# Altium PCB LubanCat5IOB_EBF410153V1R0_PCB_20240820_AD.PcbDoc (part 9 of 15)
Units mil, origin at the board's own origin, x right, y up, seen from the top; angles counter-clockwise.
Board outline 6811.02 x 4055.12 mil, 6 copper layers (TOP, GND02, ART03, ART04, PWR05, BOTTOM), stack 59.279 mil thick; 981 components, 783 nets, 3627 pads, 2669 vias.
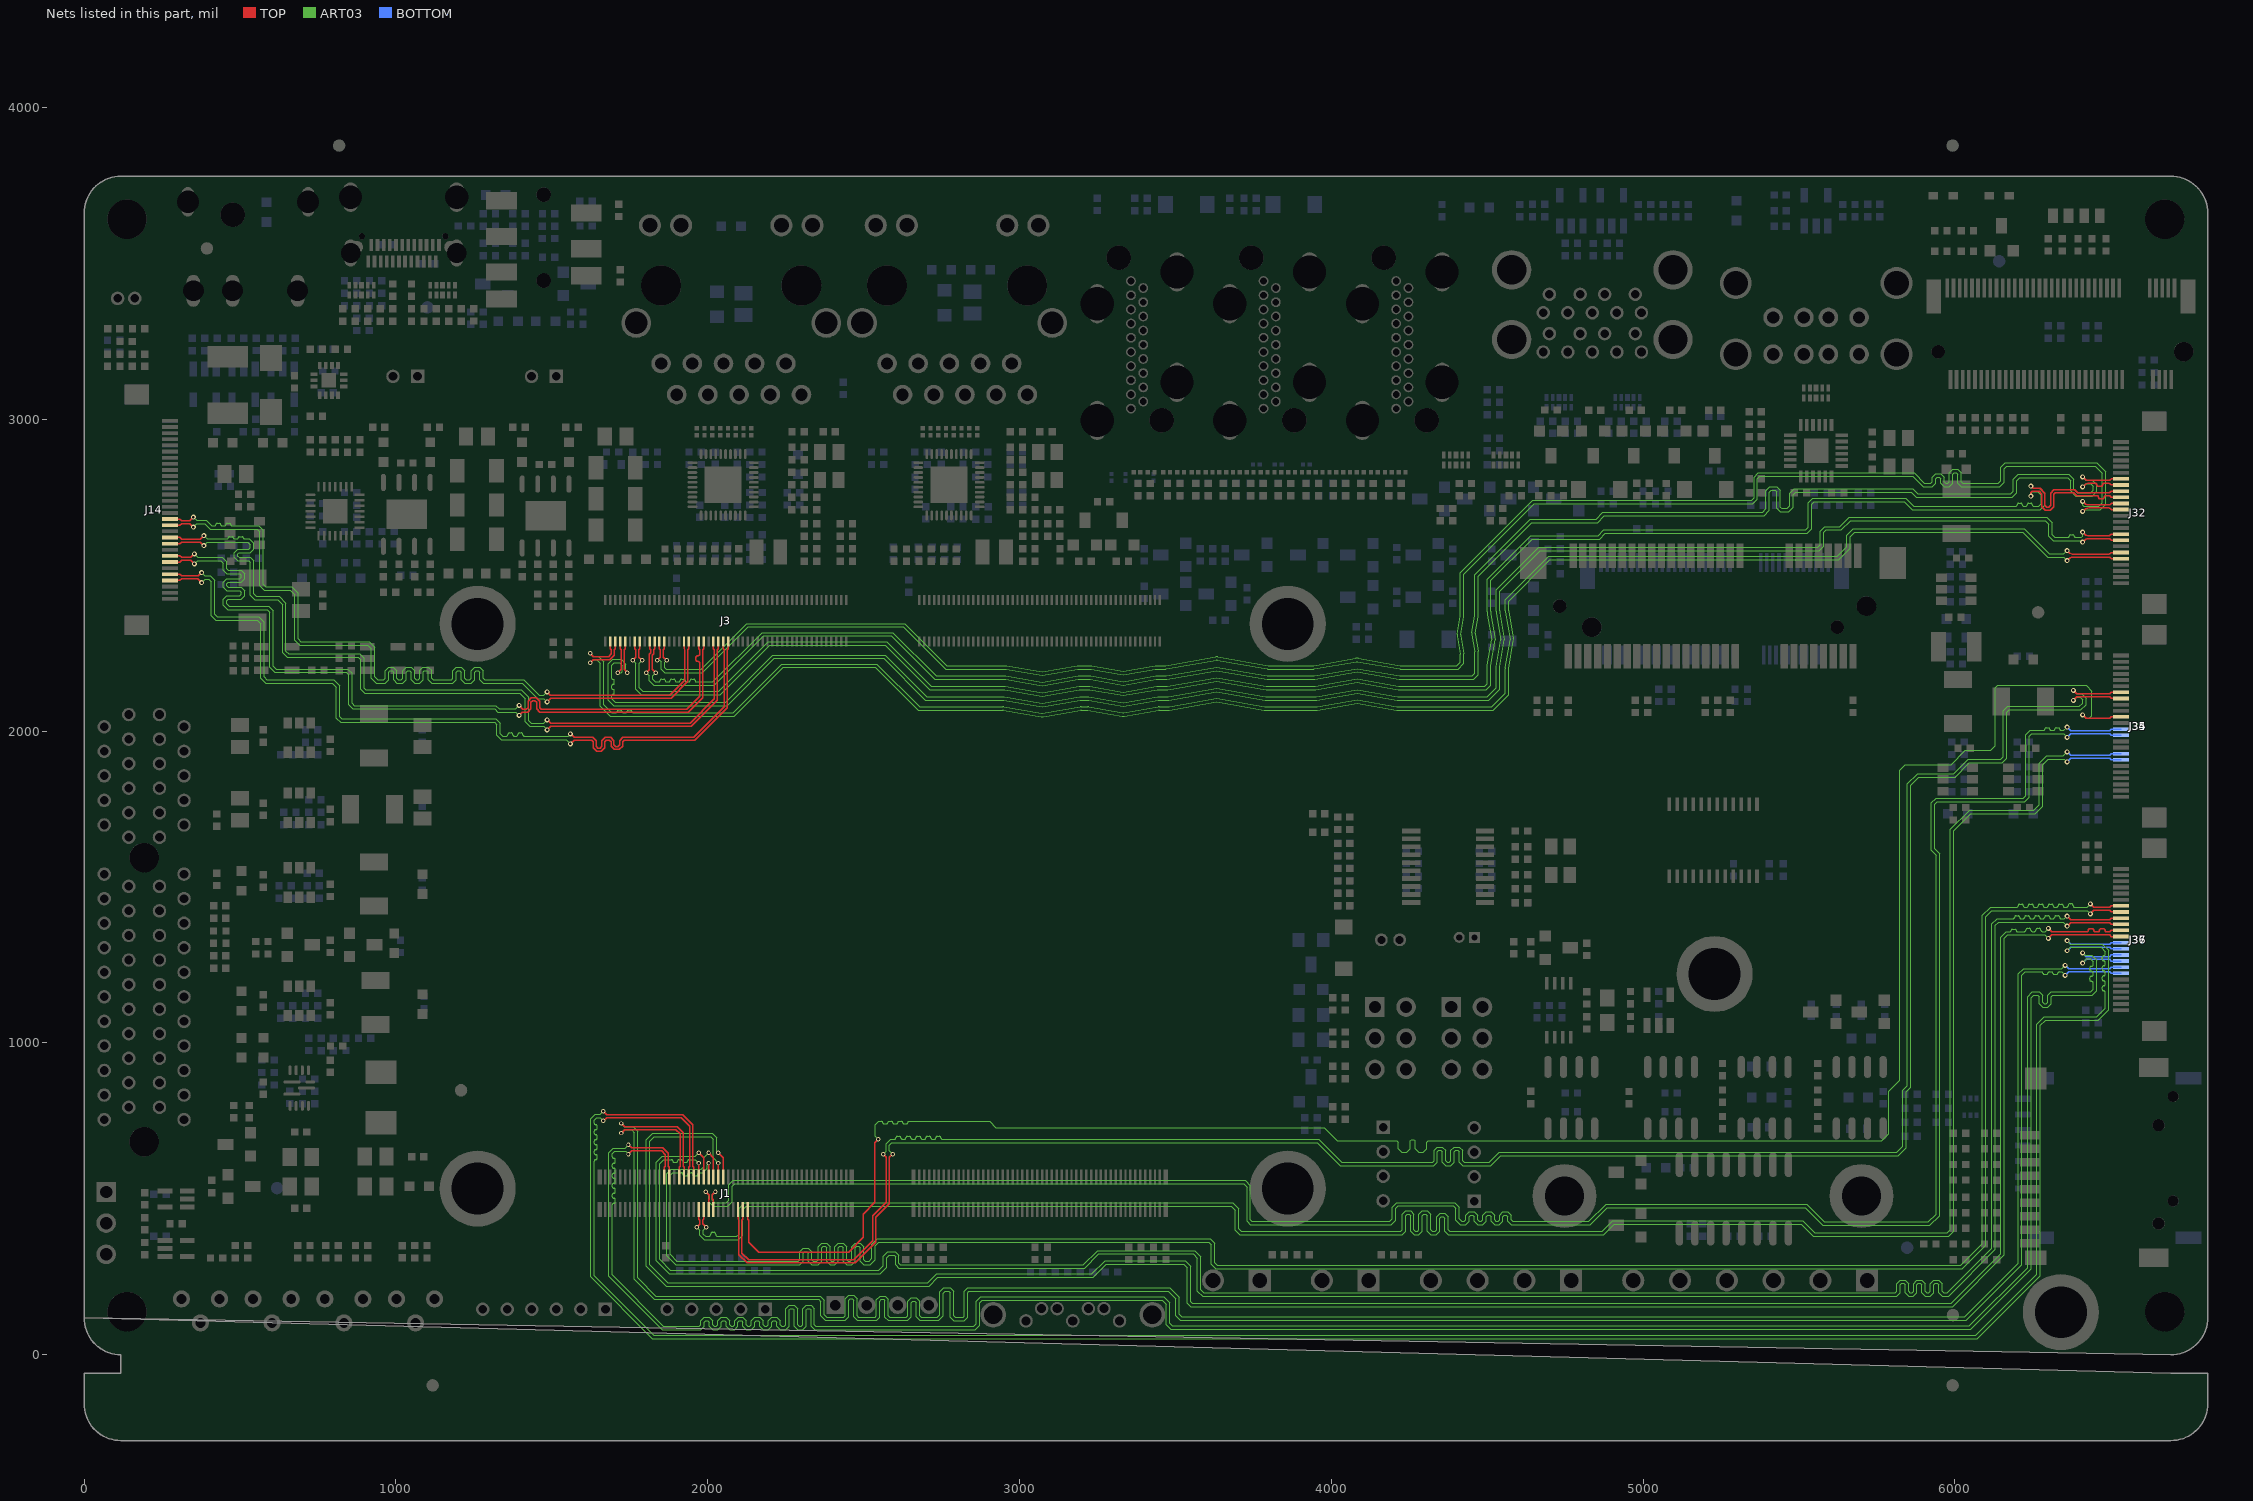
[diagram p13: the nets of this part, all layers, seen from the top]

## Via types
v1: diameter 16, hole 8, TOP to BOTTOM, 2357 vias
v2: diameter 14, hole 8, TOP to BOTTOM, 308 vias
v3: diameter 20, hole 10, TOP to BOTTOM, 4 vias

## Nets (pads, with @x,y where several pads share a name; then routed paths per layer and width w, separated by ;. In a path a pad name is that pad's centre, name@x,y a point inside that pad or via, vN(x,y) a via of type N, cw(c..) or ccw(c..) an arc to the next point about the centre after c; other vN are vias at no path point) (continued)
MIPI_CSI0_D0P: J1.60 J34.11 | length 6597.9
  TOP w4.5: J1.60@2128.84,465.62 2128.84,434.69 2131.96,431.57 2131.96,361.04 2164.5,328.5 2451.94,328.5 2499.5,376.06 2499.5,451.06 2536.5,488.06 2536.5,680.41 v2(2547.09,691) ; v1(6410,2051.75) 6421.33,2040.42 6496.49,2040.42 6501.59,2045.51 J34.11@6533.11,2045.51
  ART03 w4: v2(2547.09,691) 2537.83,700.26 2537.83,736.83 2549,748 2558.21,748 cw(c2558.21,744.5) 2561.71,744.5 ccw(c2565.21,744.5) 2565.21,741 2574.21,741 ccw(c2574.21,744.5) 2577.71,744.5 cw(c2581.21,744.5) 2581.21,748 2590.21,748 cw(c2590.21,744.5) 2593.71,744.5 ccw(c2597.21,744.5) 2597.21,741 2606.21,741 ccw(c2606.21,744.5) 2609.71,744.5 cw(c2613.21,744.5) 2613.21,748 2622.21,748 cw(c2622.21,744.5) 2625.71,744.5 ccw(c2629.21,744.5) 2629.21,741 2638.21,741 ccw(c2638.21,744.5) 2641.71,744.5 cw(c2645.21,744.5) 2645.21,748 2904.44,748 2924.44,728 3977,728 4019,686 4210.08,686 4214.77,681.31 4214.77,660.13 4225.89,649 4241.64,649 4252.77,660.13 4252.77,685.31 4257.45,690 4264.08,690 4268.77,685.31 4268.77,660.13 4279.89,649 4295.64,649 4306.77,660.13 4306.77,681.31 4311.45,686 5766,686 5788,708 5788,845 5823,880 5823,1875 5840.37,1892.37 5988.56,1892.37 6034.19,1938 6115.56,1938 6130,1952.44 6130,2139 6138,2147 6420.81,2147 6439.89,2127.92 6439.89,2049.17 6431.89,2041.17 6420.58,2041.17 v1(6410,2051.75)
MIPI_CSI0_D1N: J1.58 J34.8 | length 6596.1
  TOP w4.5: J1.58@2113.09,465.62 2113.09,434.69 2109.97,431.57 2109.97,325.03 2131,304 2469,304 2530,365 2530,445 2573.5,488.5 2573.5,632.41 v2(2562.91,643) ; v1(6380,2098.33) 6391.33,2109.66 6496.49,2109.66 6501.59,2104.57 J34.8@6533.11,2104.57
  ART03 w4: v2(2562.91,643) 2572,652.09 2572,676.56 2586.44,691 2599.41,691 ccw(c2599.41,695.5) 2603.91,695.5 cw(c2608.41,695.5) 2608.41,700 2615.41,700 cw(c2615.41,695.5) 2619.91,695.5 ccw(c2624.41,695.5) 2624.41,691 2631.41,691 ccw(c2631.41,695.5) 2635.91,695.5 cw(c2640.41,695.5) 2640.41,700 2647.41,700 cw(c2647.41,695.5) 2651.91,695.5 ccw(c2656.41,695.5) 2656.41,691 2663.41,691 ccw(c2663.41,695.5) 2667.91,695.5 cw(c2672.41,695.5) 2672.41,700 2679.41,700 cw(c2679.41,695.5) 2683.91,695.5 ccw(c2688.41,695.5) 2688.41,691 2695.41,691 ccw(c2695.41,695.5) 2699.91,695.5 cw(c2704.41,695.5) 2704.41,700 2711.41,700 cw(c2711.41,695.5) 2715.91,695.5 ccw(c2720.41,695.5) 2720.41,691 2727.41,691 ccw(c2727.41,695.5) 2731.91,695.5 cw(c2736.41,695.5) 2736.41,700 2743.41,700 cw(c2743.41,695.5) 2747.91,695.5 ccw(c2752.41,695.5) 2752.41,691 3960,691 4034,617 4324.89,617 4329.57,621.69 4329.57,654.87 4340.7,666 4356.44,666 4367.57,654.87 4367.57,621.69 4372.26,617 4378.89,617 4383.57,621.69 4383.57,654.87 4394.7,666 4410.44,666 4421.57,654.87 4421.57,621.69 4426.26,617 4507,617 4539,649 5813.44,649 5833,668.56 5833,848.56 5847,862.56 5847,1830.37 5880.37,1863.74 5996.81,1863.74 6042.44,1909.37 6148,1909.37 6156,1917.37 6156,2064.93 6170.44,2079.37 6399.67,2079.37 6409.9,2089.59 6409.9,2100.91 6401.9,2108.91 6390.58,2108.91 v1(6380,2098.33)
MIPI_CSI0_D1P: J1.56 J34.7 | length 6595
  TOP w4.5: J1.56@2097.34,465.62 2097.34,434.69 2100.47,431.57 2100.47,321.1 2127.06,294.5 2472.94,294.5 2539.5,361.06 2539.5,441.06 2583,484.56 2583,632.41 v2(2593.59,643) ; v1(6380,2130.49) 6391.33,2119.16 6496.49,2119.16 6501.59,2124.25 J34.7@6533.11,2124.25
  ART03 w4: v2(2593.59,643) 2583,653.59 2583,672 2591,680 3955.44,680 4029.44,606 4329.44,606 4340.57,617.13 4340.57,650.31 4345.26,655 4351.89,655 4356.57,650.31 4356.57,617.13 4367.7,606 4383.44,606 4394.57,617.13 4394.57,650.31 4399.26,655 4405.89,655 4410.57,650.31 4410.57,617.13 4421.7,606 4511.56,606 4543.56,638 5818,638 5844,664 5844,844 5858,858 5858,1825.81 5884.93,1852.74 6001.37,1852.74 6047,1898.37 6152.56,1898.37 6167,1912.81 6167,2060.37 6175,2068.37 6404.23,2068.37 6420.9,2085.04 6420.9,2105.47 6406.45,2119.91 6390.58,2119.91 v1(6380,2130.49)
MIPI_CSI0_D2N: J1.46 J35.12 | length 6649.3
  TOP w4.5: J1.46@2018.6,465.62 2018.6,496.56 2014.93,500.23 2014.93,512.95 v2(2025.07,523.09)
  ART03 w4: v2(2025.07,523.09) 2015.23,513.25 2015.23,495 2023.23,487 2060,487 2068,495 2068,544.56 2082.44,559 3724,559 3741,542 3741,432 3745,428 4188,428 4196,436 4196,473.56 4210.44,488 4395.56,488 4410,473.56 4410,436 4418,428 4427,428 4431.69,432.69 4431.69,446.87 4442.82,458 4458.56,458 4469.69,446.87 4469.69,432.69 4474.37,428 4481,428 4485.69,432.69 4485.69,446.87 4496.82,458 4512.56,458 4523.69,446.87 4523.69,432.69 4528.37,428 4535,428 4539.69,432.69 4539.69,446.87 4550.82,458 4566.56,458 4577.69,446.87 4577.69,432.69 4582.37,428 4826.44,428 4881.44,483 5524.56,483 5581.56,426 5915.44,426 5940,450.56 5940,1602.44 5924.75,1617.69 5924.75,1770.11 5939.64,1785 6220,1785 6228,1793 6228,1987.56 6242.44,2002 6284.62,2002 ccw(c6284.62,2006) 6288.62,2006 cw(c6292.62,2006) 6292.62,2010 6300.62,2010 cw(c6300.62,2006) 6304.62,2006 ccw(c6308.62,2006) 6308.62,2002 6316.62,2002 ccw(c6316.62,2006) 6320.62,2006 cw(c6324.62,2006) 6324.62,2010 6332.62,2010 cw(c6332.62,2006) 6336.62,2006 ccw(c6340.62,2006) 6340.62,2002 6349.62,2002 v1(6360,2012.38)
  BOTTOM w4.5: v1(6360,2012.38) 6371.33,2001.05 6496.49,2001.05 6501.59,2006.14 J35.12@6533.11,2006.14
MIPI_CSI0_D2P: J1.44 J35.11 | length 6649.3
  TOP w4.5: v2(1994.39,523.09) 2005.43,512.05 2005.43,499.13 2002.85,496.56 J1.44@2002.85,465.62
  ART03 w4: v2(1994.39,523.09) 2004.23,513.25 2004.23,490.44 2018.67,476 2064.56,476 2079,490.44 2079,540 2087,548 3719.44,548 3730,537.44 3730,427.44 3740.44,417 4192.56,417 4207,431.44 4207,469 4215,477 4391,477 4399,469 4399,431.44 4413.44,417 4431.56,417 4442.69,428.13 4442.69,442.31 4447.37,447 4454,447 4458.69,442.31 4458.69,428.13 4469.82,417 4485.56,417 4496.69,428.13 4496.69,442.31 4501.37,447 4508,447 4512.69,442.31 4512.69,428.13 4523.82,417 4539.56,417 4550.69,428.13 4550.69,442.31 4555.37,447 4562,447 4566.69,442.31 4566.69,428.13 4577.82,417 4831,417 4886,472 5520,472 5577,415 5920,415 5951,446 5951,1607 5935.75,1622.25 5935.75,1765.55 5944.2,1774 6224.56,1774 6239,1788.44 6239,1983 6247,1991 6349.22,1991 v1(6360,1980.22)
  BOTTOM w4.5: v1(6360,1980.22) 6371.33,1991.55 6496.49,1991.55 6501.59,1986.46 J35.11@6533.11,1986.46
MIPI_CSI0_D3N: J1.42 J35.8 | length 6646.4
  TOP w4.5: J1.42@1987.11,465.62 1987.11,434.69 1984.53,432.12 1984.53,419.2 v2(1995.57,408.16)
  ART03 w4: v2(1995.57,408.16) 1985.73,398.32 1985.73,387 1993.73,379 2002.73,379 ccw(c2002.73,386) 2009.73,386 cw(c2016.73,386) 2016.73,393 2018.73,393 cw(c2018.73,386) 2025.73,386 ccw(c2032.73,386) 2032.73,379 2094,379 2102,387 2102,469.56 2119.44,487 3684,487 3703,468 3703,404 3711,396 4222.63,396 4227.32,400.69 4227.32,449.87 4238.45,461 4254.19,461 4265.32,449.87 4265.32,400.69 4270,396 4276.63,396 4281.32,400.69 4281.32,449.87 4292.45,461 4308.19,461 4319.32,449.87 4319.32,400.69 4324,396 4333,396 4337.69,400.69 4337.69,441.87 4348.82,453 4364.56,453 4375.69,441.87 4375.69,400.69 4380.38,396 4869.44,396 4902.44,429 5512,429 5550,391 5976,391 5986,401 5986,1684.56 6047.07,1745.63 6252.63,1745.63 6271,1764 6271,1896.56 6295.44,1921 6347.36,1921 v1(6360,1933.64)
  BOTTOM w4.5: v1(6360,1933.64) 6371.33,1922.31 6496.49,1922.31 6501.59,1927.4 J35.8@6533.11,1927.4
MIPI_CSI0_D3P: J1.40 J35.7 | length 6647.1
  TOP w4.5: v2(1964.89,408.16) 1975.03,418.3 1975.03,431.02 1971.36,434.69 J1.40@1971.36,465.62
  ART03 w4: v2(1964.89,408.16) 1974.73,398.32 1974.73,382.44 1989.17,368 2098.56,368 2113,382.44 2113,465 2124,476 3679.44,476 3692,463.44 3692,399.44 3706.44,385 4227.19,385 4238.32,396.13 4238.32,445.31 4243,450 4249.63,450 4254.32,445.31 4254.32,396.13 4265.45,385 4281.19,385 4292.32,396.13 4292.32,445.31 4297,450 4303.63,450 4308.32,445.31 4308.32,396.13 4319.45,385 4337.56,385 4348.69,396.13 4348.69,437.31 4353.38,442 4360,442 4364.69,437.31 4364.69,396.13 4375.82,385 4874,385 4907,418 5507.44,418 5545.44,380 5980.56,380 5997,396.44 5997,1680 6051.63,1734.63 6257.19,1734.63 6282,1759.44 6282,1892 6300,1910 6351.48,1910 v1(6360,1901.48)
  BOTTOM w4.5: v1(6360,1901.48) 6371.33,1912.81 6496.49,1912.81 6501.59,1907.72 J35.7@6533.11,1907.72
MIPI_CSI1_CLK0N: J1.41 J36.10 | length 6785.3
  TOP w4.5: v2(1971.36,647.69) 1987.11,631.95 J1.41@1987.11,569.96 ; v1(6360,1374.23) 6371.33,1385.57 6496.49,1385.57 6501.59,1380.47 J36.10@6533.11,1380.47
  ART03 w4: v2(1971.36,647.69) 1960.36,636.69 1954.7,636.7 1854.44,636.7 1835,617.25 1835,301 1876,260 2553.56,260 2574,280.44 2574,311 2582,319 2597.79,319 2602.47,314.31 2602.47,288.13 2613.6,277 3209,277 3255,323 3557.44,323 3571,309.44 3571,203.44 3587.07,187.37 5813.39,187.37 5824.52,198.5 5824.52,223.68 5829.2,228.37 5835.83,228.37 5840.52,223.68 5840.52,198.5 5851.65,187.37 5867.39,187.37 5878.52,198.5 5878.52,223.68 5883.2,228.37 5889.83,228.37 5894.52,223.68 5894.52,198.5 5905.65,187.37 5921.39,187.37 5932.52,198.5 5932.52,223.68 5937.2,228.37 5943.83,228.37 5948.52,223.68 5948.52,198.5 5959.65,187.37 5980,187.37 6130,337.37 6130,1376.82 6140.19,1387 6347.23,1387 v1(6360,1374.23)
MIPI_CSI1_CLK0P: J1.39 J36.9 | length 6784.4
  TOP w4.5: J1.39@1971.36,569.96 v2(1971.36,614.69) ; v1(6360,1406.4) 6371.33,1395.07 6496.49,1395.07 6501.59,1400.16 J36.9@6533.11,1400.16
  ART03 w4: v2(1971.36,614.69) 1960.36,625.69 1949.04,625.7 1940.04,625.7 ccw(c1940.04,621.35) 1935.7,621.35 cw(c1931.35,621.35) 1931.35,617 1924.04,617 cw(c1924.04,621.35) 1919.7,621.35 ccw(c1915.35,621.35) 1915.35,625.7 1908.04,625.7 ccw(c1908.04,621.35) 1903.7,621.35 cw(c1899.35,621.35) 1899.35,617 1892.04,617 cw(c1892.04,621.35) 1887.7,621.35 ccw(c1883.35,621.35) 1883.35,625.7 1859,625.7 1846,612.7 1846,305.56 1880.56,271 2549,271 2563,285 2563,315.56 2577.44,330 2602.34,330 2613.47,318.87 2613.47,292.69 2618.16,288 3204.44,288 3250.44,334 3562,334 3582,314 3582,208 3591.63,198.37 5808.83,198.37 5813.52,203.06 5813.52,228.24 5824.65,239.37 5840.39,239.37 5851.52,228.24 5851.52,203.06 5856.2,198.37 5862.83,198.37 5867.52,203.06 5867.52,228.24 5878.65,239.37 5894.39,239.37 5905.52,228.24 5905.52,203.06 5910.2,198.37 5916.83,198.37 5921.52,203.06 5921.52,228.24 5932.65,239.37 5948.39,239.37 5959.52,228.24 5959.52,203.06 5964.2,198.37 5975.44,198.37 6119,341.93 6119,1381.37 6135.63,1398 6186.82,1398 ccw(c6186.82,1403) 6191.82,1403 cw(c6196.82,1403) 6196.82,1408 6202.82,1408 cw(c6202.82,1403) 6207.82,1403 ccw(c6212.82,1403) 6212.82,1398 6218.82,1398 ccw(c6218.82,1403) 6223.82,1403 cw(c6228.82,1403) 6228.82,1408 6234.82,1408 cw(c6234.82,1403) 6239.82,1403 ccw(c6244.82,1403) 6244.82,1398 6250.82,1398 ccw(c6250.82,1403) 6255.82,1403 cw(c6260.82,1403) 6260.82,1408 6266.82,1408 cw(c6266.82,1403) 6271.82,1403 ccw(c6276.82,1403) 6276.82,1398 6282.82,1398 ccw(c6282.82,1403) 6287.82,1403 cw(c6292.82,1403) 6292.82,1408 6298.82,1408 cw(c6298.82,1403) 6303.82,1403 ccw(c6308.82,1403) 6308.82,1398 6314.82,1398 ccw(c6314.82,1403) 6319.82,1403 cw(c6324.82,1403) 6324.82,1408 6330.82,1408 cw(c6330.82,1403) 6335.82,1403 ccw(c6340.82,1403) 6340.82,1398 6351.6,1398 v1(6360,1406.4)
MIPI_CSI1_CLK1N: J1.27 J37.10 | length 7409.5
  TOP w4.5: v2(1746,673.59) 1756.59,663 1856,663 1873.75,645.25 1873.75,604.01 1876.87,600.88 J1.27@1876.87,569.96
  ART03 w4: v2(1746,673.59) 1735.16,662.75 1697.29,662.75 1682.85,648.31 1682.85,251.6 1853.76,80.69 1978.12,80.69 1989.24,91.81 1989.24,104.31 1993.93,109 2000.56,109 2005.24,104.31 2005.24,91.81 2016.37,80.69 2032.12,80.69 2043.24,91.81 2043.24,104.31 2047.93,109 2054.56,109 2059.24,104.31 2059.24,91.81 2070.37,80.69 2086.12,80.69 2097.24,91.81 2097.24,104.31 2101.93,109 2108.56,109 2113.24,104.31 2113.24,91.81 2124.37,80.69 2140.12,80.69 2151.24,91.81 2151.24,104.31 2155.93,109 2162.56,109 2167.24,104.31 2167.24,91.81 2178.37,80.69 2194.12,80.69 2205.24,91.81 2205.24,104.31 2209.93,109 2216.56,109 2221.24,104.31 2221.24,91.81 2232.37,80.69 2250.49,80.69 2261.62,91.81 2261.62,143.31 2266.3,148 2272.93,148 2277.62,143.31 2277.62,91.81 2288.75,80.69 2304.49,80.69 2315.62,91.81 2315.62,143.31 2320.3,148 2326.93,148 2331.62,143.31 2331.62,91.81 2342.75,80.69 2857.56,80.69 2872,95.13 2872,166 2880,174 3458.44,174 3471,161.44 3471,95.44 3485.44,81 6051.19,81 6245,274.81 6245,1144 6253.37,1152.37 6265.97,1152.37 6270.66,1147.68 6270.66,1125.13 6281.78,1114 6297.53,1114 6308.66,1125.13 6308.66,1147.68 6313.34,1152.37 6440.37,1152.37 6455,1167 6455,1264.93 6439.56,1280.37 6418.69,1280.37 6418.3,1279.98 v1(6410,1288.29)
  BOTTOM w4.5: v1(6410,1288.29) 6421.33,1276.95 6497.05,1276.95 6502.14,1282.05 J37.10@6533.11,1282.05
MIPI_CSI1_CLK1P: J1.25 J37.9 | length 7407.2
  TOP w4.5: v2(1746,642.91) 1756.59,653.5 1852.06,653.5 1864.25,641.32 1864.25,604.01 1861.12,600.88 J1.25@1861.12,569.96
  ART03 w4: v2(1746,642.91) 1737.16,651.75 1701.85,651.75 1693.85,643.75 1693.85,634.75 ccw(c1698.92,634.75) 1698.92,629.67 cw(c1698.92,624.6) 1704,624.6 1704,618.75 cw(c1698.92,618.75) 1698.92,613.67 ccw(c1698.92,608.6) 1693.85,608.6 1693.85,602.75 ccw(c1698.92,602.75) 1698.92,597.67 cw(c1698.92,592.6) 1704,592.6 1704,586.75 cw(c1698.92,586.75) 1698.92,581.67 ccw(c1698.92,576.6) 1693.85,576.6 1693.85,570.75 ccw(c1698.92,570.75) 1698.92,565.67 cw(c1698.92,560.6) 1704,560.6 1704,554.75 cw(c1698.92,554.75) 1698.92,549.67 ccw(c1698.92,544.6) 1693.85,544.6 1693.85,538.75 ccw(c1698.92,538.75) 1698.92,533.67 cw(c1698.92,528.6) 1704,528.6 1704,522.75 cw(c1698.92,522.75) 1698.92,517.67 ccw(c1698.92,512.6) 1693.85,512.6 1693.85,506.75 ccw(c1698.92,506.75) 1698.92,501.67 cw(c1698.92,496.6) 1704,496.6 1704,490.75 cw(c1698.92,490.75) 1698.92,485.67 ccw(c1698.92,480.6) 1693.85,480.6 1693.85,256.15 1858.32,91.69 1973.56,91.69 1978.24,96.37 1978.24,108.87 1989.37,120 2005.12,120 2016.24,108.87 2016.24,96.37 2020.93,91.69 2027.56,91.69 2032.24,96.37 2032.24,108.87 2043.37,120 2059.12,120 2070.24,108.87 2070.24,96.37 2074.93,91.69 2081.56,91.69 2086.24,96.37 2086.24,108.87 2097.37,120 2113.12,120 2124.24,108.87 2124.24,96.37 2128.93,91.69 2135.56,91.69 2140.24,96.37 2140.24,108.87 2151.37,120 2167.12,120 2178.24,108.87 2178.24,96.37 2182.93,91.69 2189.56,91.69 2194.24,96.37 2194.24,108.87 2205.37,120 2221.12,120 2232.24,108.87 2232.24,96.37 2236.93,91.69 2245.93,91.69 2250.62,96.37 2250.62,147.87 2261.75,159 2277.49,159 2288.62,147.87 2288.62,96.37 2293.3,91.69 2299.93,91.69 2304.62,96.37 2304.62,147.87 2315.75,159 2331.49,159 2342.62,147.87 2342.62,96.37 2347.3,91.69 2853,91.69 2861,99.69 2861,170.56 2875.44,185 3463,185 3482,166 3482,100 3490,92 6046.63,92 6234,279.37 6234,1148.56 6248.81,1163.37 6270.53,1163.37 6281.66,1152.24 6281.66,1129.69 6286.34,1125 6292.97,1125 6297.66,1129.69 6297.66,1152.24 6308.78,1163.37 6435.81,1163.37 6444,1171.56 6444,1191.37 ccw(c6438,1191.37) 6438,1197.37 cw(c6438,1203.37) 6432,1203.37 6432,1207.37 cw(c6438,1207.37) 6438,1213.37 ccw(c6438,1219.37) 6444,1219.37 6444,1223.37 ccw(c6438,1223.37) 6438,1229.37 cw(c6438,1235.37) 6432,1235.37 6432,1239.37 cw(c6438,1239.37) 6438,1245.37 ccw(c6438,1251.37) 6444,1251.37 6444,1260.37 6435,1269.37 6423.25,1269.37 v1(6410,1256.12)
  BOTTOM w4.5: v1(6410,1256.12) 6421.33,1267.45 6497.05,1267.45 6502.14,1262.36 J37.9@6533.11,1262.36
MIPI_CSI1_D0N: J1.49 J36.12 | length 6788.6
  TOP w4.5: v2(2034.35,647.69) 2050.1,631.95 J1.49@2050.1,569.96 ; v1(6300,1334.86) 6311.33,1346.19 6496.49,1346.19 6501.59,1341.1 J36.12@6533.11,1341.1
  ART03 w4: v2(2034.35,647.69) 2029,653.04 2029,695.56 2014.56,710 1823.44,710 1803,689.56 1803,284 1867,220 2710.56,220 2738.56,248 3237,248 3279,290 3527.44,290 3538,279.44 3538,165.44 3549.07,154.37 5993.57,154.37 6159,319.8 6159,1335 6170,1346 6288.86,1346 v1(6300,1334.86)
MIPI_CSI1_D0P: J1.47 J36.11 | length 6785.9
  TOP w4.5: J1.47@2034.35,569.96 v2@2034.35,614.69 ; v1(6300,1367.03) 6311.33,1355.69 6422.69,1355.69 ccw(c6422.69,1360.85) 6427.84,1360.85 cw(c6432.99,1360.85) 6432.99,1366 6440.69,1366 cw(c6440.69,1360.85) 6445.84,1360.85 ccw(c6450.99,1360.85) 6450.99,1355.69 6458.69,1355.69 ccw(c6458.69,1360.85) 6463.84,1360.85 cw(c6468.99,1360.85) 6468.99,1366 6476.69,1366 cw(c6476.69,1360.85) 6481.84,1360.85 ccw(c6486.99,1360.85) 6486.99,1355.69 6496.49,1355.69 6501.59,1360.79 J36.11@6533.11,1360.79
  ART03 w4: v2(2034.35,614.69) 2018,631.04 2018,691 2010,699 1828,699 1814,685 1814,288.56 1871.56,231 2706,231 2734,259 3232.44,259 3274.44,301 3532,301 3549,284 3549,170 3553.63,165.37 5989.01,165.37 6148,324.36 6148,1339.56 6165.44,1357 6177.19,1357 ccw(c6177.19,1360.5) 6180.69,1360.5 cw(c6184.19,1360.5) 6184.19,1364 6193.19,1364 cw(c6193.19,1360.5) 6196.69,1360.5 ccw(c6200.19,1360.5) 6200.19,1357 6222.98,1357 ccw(c6222.98,1362) 6227.98,1362 cw(c6232.98,1362) 6232.98,1367 6238.98,1367 cw(c6238.98,1362) 6243.98,1362 ccw(c6248.98,1362) 6248.98,1357 6254.98,1357 ccw(c6254.98,1362) 6259.98,1362 cw(c6264.98,1362) 6264.98,1367 6270.98,1367 cw(c6270.98,1362) 6275.98,1362 ccw(c6280.98,1362) 6280.98,1357 6289.98,1357 v1(6300,1367.03)
MIPI_CSI1_D1N: J1.45 J36.8 | length 6788.2
  TOP w4.5: v2(2002.86,647.69) 2018.6,631.95 J1.45@2018.6,569.96 ; v1(6435,1413.61) 6446.33,1424.93 6496.49,1424.93 6501.59,1419.84 J36.8@6533.11,1419.84
  ART03 w4: v2(2002.86,647.69) 1987,631.84 1987,603 1979,595 1883.44,595 1869,580.56 1869,317 1897,289 2295.68,289 2306.81,300.13 2306.81,325.31 2311.49,330 2318.12,330 2322.81,325.31 2322.81,300.13 2333.94,289 2354.22,289 2365.35,300.13 2365.35,342.31 2370.04,347 2376.67,347 2381.35,342.31 2381.35,300.13 2392.48,289 2408.22,289 2419.35,300.13 2419.35,342.31 2424.04,347 2430.67,347 2435.35,342.31 2435.35,300.13 2446.48,289 2462.22,289 2473.35,300.13 2473.35,342.31 2478.04,347 2484.67,347 2489.35,342.31 2489.35,300.13 2500.48,289 2522,289 2538,305 2538,350 2548,360 3607,360 3615,352 3615,290.44 3629.44,276 6024.19,276 6099,350.81 6099,1404 6119,1424 6424.6,1424 v1(6435,1413.61)
MIPI_CSI1_D1P: J1.43 J36.7 | length 6786.6
  TOP w4.5: J1.43@2002.85,569.96 v2(2002.85,614.69) ; v1(6435,1445.77) 6446.33,1434.43 6496.49,1434.43 6501.59,1439.53 J36.7@6533.11,1439.53
  ART03 w4: v2(2002.85,614.69) 1998,609.84 1998,598.44 1983.56,584 1973.57,584 ccw(c1973.57,579) 1968.57,579 cw(c1963.57,579) 1963.57,574 1957.57,574 cw(c1957.57,579) 1952.57,579 ccw(c1947.57,579) 1947.57,584 1941.57,584 ccw(c1941.57,579) 1936.57,579 cw(c1931.57,579) 1931.57,574 1925.57,574 cw(c1925.57,579) 1920.57,579 ccw(c1915.57,579) 1915.57,584 1888,584 1880,576 1880,321.56 1901.56,300 2291.12,300 2295.81,304.69 2295.81,329.87 2306.94,341 2322.68,341 2333.81,329.87 2333.81,304.69 2338.49,300 2349.67,300 2354.35,304.69 2354.35,346.87 2365.48,358 2381.22,358 2392.35,346.87 2392.35,304.69 2397.04,300 2403.67,300 2408.35,304.69 2408.35,346.87 2419.48,358 2435.22,358 2446.35,346.87 2446.35,304.69 2451.04,300 2457.67,300 2462.35,304.69 2462.35,346.87 2473.48,358 2489.22,358 2500.35,346.87 2500.35,304.69 2505.04,300 2517.44,300 2527,309.56 2527,354.56 2543.44,371 3611.56,371 3626,356.56 3626,295 3634,287 6019.63,287 6088,355.37 6088,1408.56 6114.44,1435 6198.34,1435 ccw(c6198.34,1440) 6203.34,1440 cw(c6208.34,1440) 6208.34,1445 6214.34,1445 cw(c6214.34,1440) 6219.34,1440 ccw(c6224.34,1440) 6224.34,1435 6230.34,1435 ccw(c6230.34,1440) 6235.34,1440 cw(c6240.34,1440) 6240.34,1445 6246.34,1445 cw(c6246.34,1440) 6251.34,1440 ccw(c6256.34,1440) 6256.34,1435 6262.34,1435 ccw(c6262.34,1440) 6267.34,1440 cw(c6272.34,1440) 6272.34,1445 6278.34,1445 cw(c6278.34,1440) 6283.34,1440 ccw(c6288.34,1440) 6288.34,1435 6294.34,1435 ccw(c6294.34,1440) 6299.34,1440 cw(c6304.34,1440) 6304.34,1445 6310.34,1445 cw(c6310.34,1440) 6315.34,1440 ccw(c6320.34,1440) 6320.34,1435 6326.34,1435 ccw(c6326.34,1440) 6331.34,1440 cw(c6336.34,1440) 6336.34,1445 6342.34,1445 cw(c6342.34,1440) 6347.34,1440 ccw(c6352.34,1440) 6352.34,1435 6358.34,1435 ccw(c6358.34,1440) 6363.34,1440 cw(c6370.34,1440) 6370.34,1447 6372.34,1447 cw(c6372.34,1440) 6379.34,1440 ccw(c6384.34,1440) 6384.34,1435 6424.23,1435 v1(6435,1445.77)
MIPI_CSI1_D2N: J1.37 J37.12 | length 7404.7
  TOP w4.5: v2(1665,780.59) 1675.59,770 1919.44,770 1952.49,736.95 1952.49,604.01 1955.61,600.88 J1.37@1955.61,569.96
  ART03 w4: v2(1665,780.59) 1655.16,770.75 1639.29,770.75 1624.85,756.31 1624.85,249.15 1822.32,51.69 6072.31,51.69 6274,253.37 6274,1055.81 6291.56,1073.37 6460,1073.37 6493,1106.37 6493,1297.63 6473.56,1317.08 6370.58,1317.08 v1(6360,1327.65)
  BOTTOM w4.5: v1(6360,1327.65) 6371.33,1316.33 6497.05,1316.33 6502.14,1321.42 J37.12@6533.11,1321.42
MIPI_CSI1_D2P: J1.35 J37.11 | length 7403.5
  TOP w4.5: v2(1665,749.91) 1675.59,760.5 1915.5,760.5 1942.99,733.01 1942.99,604.01 1939.86,600.88 J1.35@1939.86,569.96
  ART03 w4: v2(1665,749.91) 1655.16,759.75 1643.85,759.75 1635.85,751.75 1635.85,742.75 ccw(c1640.92,742.75) 1640.92,737.67 cw(c1640.92,732.6) 1646,732.6 1646,726.75 cw(c1640.92,726.75) 1640.92,721.67 ccw(c1640.92,716.6) 1635.85,716.6 1635.85,710.75 ccw(c1640.92,710.75) 1640.92,705.67 cw(c1640.92,700.6) 1646,700.6 1646,694.75 cw(c1640.92,694.75) 1640.92,689.67 ccw(c1640.92,684.6) 1635.85,684.6 1635.85,678.75 ccw(c1640.92,678.75) 1640.92,673.67 cw(c1640.92,668.6) 1646,668.6 1646,662.75 cw(c1640.92,662.75) 1640.92,657.67 ccw(c1640.92,652.6) 1635.85,652.6 1635.85,646.75 ccw(c1640.92,646.75) 1640.92,641.67 cw(c1640.92,636.6) 1646,636.6 1646,630.75 cw(c1640.92,630.75) 1640.92,625.67 ccw(c1640.92,620.6) 1635.85,620.6 1635.85,253.71 1826.87,62.69 6067.76,62.69 6263,257.93 6263,1060.37 6287,1084.37 6455.44,1084.37 6482,1110.93 6482,1162.41 ccw(c6477.5,1162.41) 6477.5,1166.91 cw(c6477.5,1171.41) 6473,1171.41 6473,1178.41 cw(c6477.5,1178.41) 6477.5,1182.91 ccw(c6477.5,1187.41) 6482,1187.41 6482,1194.41 ccw(c6477.5,1194.41) 6477.5,1198.91 cw(c6477.5,1203.41) 6473,1203.41 6473,1210.41 cw(c6477.5,1210.41) 6477.5,1214.91 ccw(c6477.5,1219.41) 6482,1219.41 6482,1226.41 ccw(c6477.5,1226.41) 6477.5,1230.91 cw(c6477.5,1235.41) 6473,1235.41 6473,1242.41 cw(c6477.5,1242.41) 6477.5,1246.91 ccw(c6477.5,1251.41) 6482,1251.41 6482,1258.41 ccw(c6477.5,1258.41) 6477.5,1262.91 cw(c6477.5,1267.41) 6473,1267.41 6473,1274.41 cw(c6477.5,1274.41) 6477.5,1278.91 ccw(c6477.5,1283.41) 6482,1283.41 6482,1293.08 6469,1306.08 6370.58,1306.08 v1(6360,1295.49)
  BOTTOM w4.5: v1(6360,1295.49) 6371.33,1306.83 6497.05,1306.83 6502.14,1301.73 J37.11@6533.11,1301.73
MIPI_CSI1_D3N: J1.33 J37.8 | length 7407.1
  TOP w4.5: v2(1723,741.59) 1733.59,731 1902,731 1920.99,712.01 1920.99,604.01 1924.11,600.88 J1.33@1924.11,569.96
  ART03 w4: v2(1723,741.59) 1732.84,731.75 1761.25,731.75 1776,717 1776,246 1834,188 2361,188 2374,175 2374,128.69 2382,120.69 2436.38,120.69 2441.06,125.37 2441.06,179.87 2452.19,191 2467.93,191 2479.06,179.87 2479.06,125.37 2483.75,120.69 2537.39,120.69 2541.39,124.69 2541.39,176.56 2552.83,188 2568.95,188 2579.39,177.56 2579.39,124.69 2583.39,120.69 2636.9,120.69 2641.58,125.37 2641.58,170.87 2652.71,182 2668.45,182 2679.58,170.87 2679.58,125.37 2684.27,120.69 2737,120.69 2745,128.69 2745,201.56 2757.44,214 2777.56,214 2788.69,202.87 2788.69,124.69 2793.37,120 2819,120 2823,124 2823,203.56 2833.44,214 3481.56,214 3512,183.56 3512,129 3520,121 6031.63,121 6204,293.37 6204,1221.56 6220.78,1238.34 6343.42,1238.34 v1(6354,1248.91)
  BOTTOM w4.5: v1(6354,1248.91) 6365.33,1237.59 6497.05,1237.59 6502.14,1242.68 J37.8@6533.11,1242.68
MIPI_CSI1_D3P: J1.31 J37.7 | length 7408.1
  TOP w4.5: v2(1723,710.91) 1733.59,721.5 1898.06,721.5 1911.49,708.07 1911.49,604.01 1908.37,600.88 J1.31@1908.37,569.96
  ART03 w4: v2(1723,710.91) 1732.84,720.75 1756.69,720.75 1765,712.44 1765,241.44 1829.44,177 2356.44,177 2363,170.44 2363,124.13 2377.44,109.69 2440.93,109.69 2452.06,120.81 2452.06,175.31 2456.75,180 2463.38,180 2468.06,175.31 2468.06,120.81 2479.19,109.69 2541.95,109.69 2552.39,120.13 2552.39,172 2557.39,177 2564.39,177 2568.39,173 2568.39,120.13 2578.83,109.69 2641.45,109.69 2652.58,120.81 2652.58,166.31 2657.27,171 2663.9,171 2668.58,166.31 2668.58,120.81 2679.71,109.69 2741.56,109.69 2756,124.13 2756,197 2762,203 2773,203 2777.69,198.31 2777.69,120.13 2788.82,109 2823.56,109 2834,119.44 2834,199 2838,203 3477,203 3501,179 3501,124.44 3515.44,110 6036.19,110 6215,288.81 6215,1217 6225.34,1227.34 6278.97,1227.34 cw(c6278.97,1223.67) 6282.63,1223.67 ccw(c6286.3,1223.67) 6286.3,1220 6294.97,1220 ccw(c6294.97,1223.67) 6298.63,1223.67 cw(c6302.3,1223.67) 6302.3,1227.33 6310.97,1227.34 cw(c6310.97,1223.67) 6314.63,1223.67 ccw(c6318.3,1223.67) 6318.3,1220 6326.97,1220 ccw(c6326.97,1223.67) 6330.63,1223.67 cw(c6334.3,1223.67) 6334.3,1227.33 6343.42,1227.34 v1(6354,1216.75)
  BOTTOM w4.5: v1(6354,1216.75) 6365.33,1228.09 6497.05,1228.09 6502.14,1222.99 J37.7@6533.11,1222.99
MIPI_DPHY0_RX_CLKN: J3.15 J32.10 | length 5819.6
  TOP w4.5: J3.15@1782.39,2286.88 1782.39,2263.82 1779.26,2260.7 1779.26,2237.5 v2(1789.85,2226.91) ; v1(6244.17,2753.54) 6244.17,2764.37 6248.67,2768.87 6270.23,2768.87 6279.5,2759.6 6279.5,2719.84 6290.34,2709 6305.67,2709 6316.5,2719.84 6316.5,2759.6 6321.78,2764.87 6380.69,2764.87 6390.55,2755.01 6455.83,2755.01 cw(c6455.83,2750.01) 6460.84,2750.01 ccw(c6465.84,2750.01) 6465.84,2745 6473.83,2745 ccw(c6473.83,2750.01) 6478.84,2750.01 cw(c6483.84,2750.01) 6483.84,2755.01 6493.34,2755.01 cw(c6493.34,2747.41) 6498.72,2752.78 6499.36,2752.15 ccw(c6504.74,2757.53) 6504.74,2749.92 J32.10@6533.11,2749.92
  ART03 w4: v2(1789.85,2226.91) 1780.01,2217.07 1780.01,2138.99 1791,2128 2036,2128 2195,2287 2574.56,2287 2717.56,2144 2953.64,2144 3072.35,2123.39 3191.06,2144 3225.64,2144 3333.13,2125.34 3440.62,2144 3474.24,2144 3633.25,2171.61 3792.26,2144 3948.93,2144 4082.59,2167.21 4216.26,2144 4492,2144 4500,2152 4500,2201.03 4500.84,2210.79 4514.99,2292.28 4500.84,2373.77 4500,2383.52 4500,2487.56 4639.44,2627 4856,2627 4874,2645 5522,2645 5530,2653 5530,2731.56 5544.44,2746 5843,2746 5868,2721 6195.23,2721 ccw(c6195.23,2726) 6200.23,2726 cw(c6205.23,2726) 6205.23,2731 6211.23,2731 cw(c6211.23,2726) 6216.23,2726 ccw(c6221.23,2726) 6221.23,2721 6227.23,2721 ccw(c6227.23,2726) 6232.23,2726 cw(c6237.23,2726) 6237.23,2731 6243.23,2731 cw(c6243.23,2726) 6248.23,2726 ccw(c6253.23,2726) 6253.23,2721 6269,2721 6277,2729 6277,2756.12 6266,2767.12 6248.17,2767.12 6244.17,2763.12 v1(6244.17,2753.54)
MIPI_DPHY0_RX_CLKP: J3.13 J32.9 | length 5822.3
  TOP w4.5: v2(1759.17,2226.91) 1769.76,2237.5 1769.76,2260.7 1766.64,2263.82 J3.13@1766.64,2286.88 ; v1(6244.17,2785.7) 6251.5,2778.37 6274.17,2778.37 6289,2763.53 6289,2723.77 6294.28,2718.5 6301.73,2718.5 6307,2723.77 6307,2763.53 6317.84,2774.37 6384.63,2774.37 6394.49,2764.51 6493.34,2764.51 ccw(c6493.34,2772.12) 6498.72,2766.74 6499.36,2767.38 cw(c6504.74,2762) 6504.74,2769.61 J32.9@6533.11,2769.61
  ART03 w4: v2(1759.17,2226.91) 1769.01,2217.07 1769.01,2134.43 1786.44,2117 2040.56,2117 2199.56,2276 2570,2276 2713,2133 2952.69,2133 3072.35,2112.22 3192.01,2133 3224.69,2133 3333.13,2114.17 3441.57,2133 3475.19,2133 3633.25,2160.44 3791.31,2133 3949.88,2133 4082.59,2156.04 4215.31,2133 4496.56,2133 4511,2147.44 4511,2200.56 4511.76,2209.37 4526.15,2292.28 4511.76,2375.18 4511,2383.99 4511,2483 4644,2616 4860.56,2616 4878.56,2634 5526.56,2634 5541,2648.44 5541,2727 5549,2735 5838.44,2735 5863.44,2710 6273.56,2710 6288,2724.44 6288,2760.68 6270.56,2778.12 6251.75,2778.12 v1(6244.17,2785.7)
MIPI_DPHY0_RX_D0N: J3.25 J32.12 | length 5818.3
  TOP w4.5: J3.25@1861.13,2286.88 1861.13,2263.82 1858,2260.7 1858,2237.5 v2(1868.59,2226.91) ; v1(6410,2704.31) 6415.98,2710.3 cw(c6428.89,2697.39) 6428.89,2715.64 6493.34,2715.64 cw(c6493.34,2708.04) 6498.72,2713.41 6499.36,2712.78 ccw(c6504.74,2718.16) 6504.74,2710.55 J32.12@6533.11,2710.55
  ART03 w4: v2(1868.59,2226.91) 1861.75,2220.07 1861.75,2202.76 1866.75,2197.76 1978.76,2197.76 2126,2345 2632.56,2345 2767.56,2210 2959.33,2210 3072.35,2190.38 3185.37,2210 3231.33,2210 3333.13,2192.33 3434.93,2210 3467.87,2210 ccw(c3467.86,2218) 3469.23,2210.12 3630,2238.03 cw(c3633.25,2219.31) 3636.5,2238.03 3797.27,2210.12 ccw(c3798.64,2218) 3798.64,2210 3942.55,2210 ccw(c3942.55,2218) 3943.92,2210.12 4079.34,2233.63 cw(c4082.59,2214.91) 4085.84,2233.63 4221.27,2210.12 ccw(c4222.64,2218) 4222.64,2210 4402.44,2210 4414,2221.56 4414,2245.22 ccw(c4406,2245.21) 4413.88,2246.58 4403.88,2304.2 cw(c4422.6,2307.45) 4403.88,2310.7 4413.88,2368.32 ccw(c4406,2369.69) 4414,2369.69 4414,2508 4646,2740 5348,2740 5356,2748 5356,2814.56 5369.44,2828 5869.56,2828 5902.56,2795 5923.56,2795 5928.24,2799.69 5928.24,2813.87 5939.37,2825 5955.11,2825 5966.24,2813.87 5966.24,2799.69 5970.93,2795 5977.56,2795 5982.24,2799.69 5982.24,2827.87 5993.37,2839 6009.11,2839 6020.24,2827.87 6020.24,2799.69 6024.93,2795 6139,2795 6147,2803 6147,2845.56 6161.44,2860 6455.56,2860 6484,2831.56 6484,2727.34 6466.56,2709.89 6415.58,2709.89 v1(6410,2704.31)
MIPI_DPHY0_RX_D0P: J3.23 J32.11 | length 5818.2
  TOP w4.5: v2(1837.91,2226.91) 1848.5,2237.5 1848.5,2260.7 1845.38,2263.82 J3.23@1845.38,2286.88 ; v1(6410,2736.47) 6415.98,2730.49 ccw(c6428.89,2743.4) 6428.89,2725.14 6493.34,2725.14 ccw(c6493.34,2732.75) 6498.72,2727.37 6499.36,2728.01 cw(c6504.74,2722.63) 6504.74,2730.24 J32.11@6533.11,2730.24
  ART03 w4: v2(1837.91,2226.91) 1846.09,2226.91 1850.75,2222.25 1850.75,2198.2 1862.2,2186.76 1983.32,2186.76 2130.56,2334 2628,2334 2763,2199 2958.38,2199 3072.35,2179.21 3186.32,2199 3230.38,2199 3333.13,2181.16 3435.88,2199 3467.87,2199 ccw(c3467.87,2218) 3471.12,2199.28 3631.88,2227.2 cw(c3633.25,2219.31) 3634.62,2227.2 3795.39,2199.28 ccw(c3798.64,2218) 3798.64,2199 3942.55,2199 ccw(c3942.55,2218) 3945.8,2199.28 4081.22,2222.8 cw(c4082.59,2214.91) 4083.96,2222.8 4219.39,2199.28 ccw(c4222.64,2218) 4222.64,2199 4407,2199 4425,2217 4425,2245.22 ccw(c4406,2245.22) 4424.72,2248.46 4414.72,2306.08 cw(c4422.6,2307.45) 4414.71,2308.82 4424.72,2366.44 ccw(c4406,2369.69) 4425,2369.69 4425,2503.44 4650.56,2729 5352.56,2729 5367,2743.44 5367,2810 5374,2817 5865,2817 5898,2784 5928.11,2784 5939.24,2795.13 5939.24,2809.31 5943.93,2814 5950.56,2814 5955.24,2809.31 5955.24,2795.13 5966.37,2784 5982.11,2784 5993.24,2795.13 5993.24,2823.31 5997.93,2828 6004.56,2828 6009.24,2823.31 6009.24,2795.13 6020.37,2784 6143.56,2784 6158,2798.44 6158,2841 6166,2849 6451,2849 6473,2827 6473,2731.89 6462,2720.89 6414.11,2720.89 6410,2725 v1(6410,2736.47)
MIPI_DPHY0_RX_D1N: J3.21 J32.8 | length 5814.9
  TOP w4.5: J3.21@1829.63,2286.88 1829.63,2263.82 1826.51,2260.7 1826.51,2247.51 1822,2243 1822,2198.37 v2(1833.59,2186.78) ; v1(6410,2783.05) 6415.98,2789.04 cw(c6428.89,2776.13) 6428.89,2794.38 6451.11,2794.38 cw(c6451.11,2789.69) 6455.8,2789.69 ccw(c6460.49,2789.69) 6460.49,2785 6469.11,2785 ccw(c6469.11,2789.69) 6473.8,2789.69 cw(c6478.49,2789.69) 6478.49,2794.38 6493.34,2794.38 cw(c6493.34,2786.78) 6498.72,2792.15 6499.36,2791.52 ccw(c6504.74,2796.9) 6504.74,2789.29 J32.8@6533.11,2789.29
  ART03 w4: v2(1833.59,2186.78) 1823.75,2176.94 1823.75,2165.63 1831.75,2157.63 1842.89,2157.63 ccw(c1842.89,2162.32) 1847.58,2162.32 cw(c1852.26,2162.32) 1852.26,2167 1858.89,2167 cw(c1858.89,2162.32) 1863.58,2162.32 ccw(c1868.26,2162.32) 1868.26,2157.63 1874.89,2157.63 ccw(c1874.89,2162.32) 1879.58,2162.32 cw(c1884.26,2162.32) 1884.26,2167 1890.89,2167 cw(c1890.89,2162.32) 1895.58,2162.32 ccw(c1900.26,2162.32) 1900.26,2157.63 1906.89,2157.63 ccw(c1906.89,2162.32) 1911.58,2162.32 cw(c1916.26,2162.32) 1916.26,2167 1922.89,2167 cw(c1922.89,2162.32) 1927.58,2162.32 ccw(c1932.26,2162.32) 1932.26,2157.63 1938.89,2157.63 ccw(c1938.89,2162.32) 1943.58,2162.32 cw(c1948.26,2162.32) 1948.26,2167 1954.89,2167 cw(c1954.89,2162.32) 1959.58,2162.32 ccw(c1964.26,2162.32) 1964.26,2157.63 2017.07,2157.63 2175.44,2316 2593.56,2316 2732.56,2177 2956.49,2177 3072.35,2156.88 3188.22,2177 3228.49,2177 3333.13,2158.83 3437.77,2177 3471.4,2177 3633.25,2205.1 3795.1,2177 3946.09,2177 4082.59,2200.7 4219.1,2177 4452,2177 4460,2185 4460,2253.47 ccw(c4452,2253.47) 4459.88,2254.84 4450.51,2308.83 cw(c4469.23,2312.08) 4450.51,2315.33 4459.88,2369.32 ccw(c4452,2370.69) 4460,2370.69 4460,2501 4639,2680 4849.44,2680 4871.44,2702 5383.44,2702 5394,2712.56 5394,2770.95 5406.05,2783 5429.16,2783 5440.29,2771.87 5440.29,2718.69 5444.98,2714 5463,2714 5471,2722 5471,2762.16 5485.44,2776.61 5865.39,2776.61 5881,2761 6179,2761 6187,2769 6187,2807 6204,2824 6366,2824 6382,2808 6382,2775 6392,2765 6436,2765 6444,2773 6444,2785.63 6436,2793.63 6420.58,2793.63 v1(6410,2783.05)
MIPI_DPHY0_RX_D1P: J3.19 J32.7 | length 5815.3
  TOP w4.5: v2(1802.91,2186.78) 1812.5,2196.37 1812.5,2246.94 1817.01,2251.44 1817.01,2260.7 1813.88,2263.82 J3.19@1813.88,2286.88 ; v1(6410,2815.21) 6415.98,2809.23 ccw(c6428.89,2822.14) 6428.89,2803.88 6493.34,2803.88 ccw(c6493.34,2811.49) 6498.72,2806.11 6499.36,2806.75 cw(c6504.74,2801.37) 6504.74,2808.98 J32.7@6533.11,2808.98
  ART03 w4: v2(1802.91,2186.78) 1812.75,2176.94 1812.75,2161.07 1827.19,2146.63 2021.63,2146.63 2180,2305 2589,2305 2728,2166 2955.54,2166 3072.35,2145.72 3189.16,2166 3227.54,2166 3333.13,2147.67 3438.72,2166 3472.35,2166 3633.25,2193.94 3794.15,2166 3947.03,2166 4082.59,2189.54 4218.15,2166 4456.56,2166 4471,2180.44 4471,2253.47 ccw(c4452,2253.47) 4470.72,2256.72 4461.35,2310.71 cw(c4469.23,2312.08) 4461.34,2313.45 4470.72,2367.44 ccw(c4452,2370.69) 4471,2370.69 4471,2496.44 4643.56,2669 4854,2669 4876,2691 5388,2691 5405,2708 5405,2766.39 5410.61,2772 5424.61,2772 5429.29,2767.31 5429.29,2714.13 5440.42,2703 5467.56,2703 5482,2717.44 5482,2757.61 5490,2765.61 5860.84,2765.61 5876.44,2750 6183.56,2750 6198,2764.44 6198,2802.44 6208.56,2813 6361.44,2813 6371,2803.44 6371,2770.44 6387.44,2754 6440.56,2754 6455,2768.44 6455,2790.19 6440.56,2804.63 6420.58,2804.63 v1(6410,2815.21)
MIPI_DPHY0_RX_D2N: J3.9 J32.17 | length 5822.3
  TOP w4.5: J3.9@1735.14,2286.88 1735.14,2263.82 1732.02,2260.7 1732.02,2197.59 v2(1742.61,2187) ; v1(6410,2605.89) 6415.98,2611.87 cw(c6428.89,2598.96) 6428.89,2617.22 6493.34,2617.22 cw(c6493.34,2609.61) 6498.72,2614.99 6499.36,2614.35 ccw(c6504.74,2619.73) 6504.74,2612.12 J32.17@6533.11,2612.12
  ART03 w4: v2(1742.61,2187) 1737.77,2191.84 1737.77,2214.56 1722.33,2230 1695.44,2230 1681,2215.56 1681,2099.44 1699.44,2081 2062,2081 2214,2233 2564.44,2233 2698.44,2099 2949.76,2099 3072.35,2077.71 3194.94,2099 3221.76,2099 3333.13,2079.66 3444.5,2099 3478.12,2099 3633.25,2125.93 3788.38,2099 3952.81,2099 4082.59,2121.53 4212.38,2099 4504.56,2099 4540,2134.44 4540,2199.31 4540.55,2205.64 4555.59,2292.28 4540.55,2378.91 4540,2385.24 4540,2448.44 4669.56,2578 5564.56,2578 5579,2592.44 5579,2637 5587,2645 5636,2645 5666.37,2675.37 6290.07,2675.37 6302,2663.44 6302,2624.91 6316.44,2610.47 6405.42,2610.47 v1(6410,2605.89)
MIPI_DPHY0_RX_D2P: J3.7 J32.16 | length 5819.5
  TOP w4.5: v2(1711.93,2187) 1722.52,2197.59 1722.52,2260.7 1719.39,2263.82 J3.7@1719.39,2286.88 ; v1(6410,2638.05) 6415.98,2632.06 ccw(c6428.89,2644.97) 6428.89,2626.72 6493.34,2626.72 ccw(c6493.34,2634.33) 6498.72,2628.95 6499.36,2629.58 cw(c6504.74,2624.2) 6504.74,2631.81 J32.16@6533.11,2631.81
  ART03 w4: v2(1711.93,2187) 1722.77,2187 1726.77,2191 1726.77,2210 1717.77,2219 1700,2219 1692,2211 1692,2170 ccw(c1696.5,2170) 1696.5,2165.5 cw(c1696.5,2161) 1701,2161 1701,2154 cw(c1696.5,2154) 1696.5,2149.5 ccw(c1696.5,2145) 1692,2145 1692,2138 ccw(c1696.5,2138) 1696.5,2133.5 cw(c1696.5,2129) 1701,2129 1701,2122 cw(c1696.5,2122) 1696.5,2117.5 ccw(c1696.5,2113) 1692,2113 1692,2104 1704,2092 2057.44,2092 2209.44,2244 2569,2244 2703,2110 2950.71,2110 3072.35,2088.88 3193.99,2110 3222.71,2110 3333.13,2090.83 3443.55,2110 3477.18,2110 3633.25,2137.1 3789.33,2110 3951.86,2110 4082.59,2132.7 4213.33,2110 4500,2110 4529,2139 4529,2199.79 4529.63,2207.06 4544.42,2292.28 4529.63,2377.5 4529,2384.77 4529,2453 4665,2589 5560,2589 5568,2597 5568,2641.56 5582.44,2656 5631.44,2656 5661.81,2686.37 6294.63,2686.37 6313,2668 6313,2629.47 6321,2621.47 6362.95,2621.47 ccw(c6362.95,2625.23) 6366.72,2625.23 cw(c6370.49,2625.23) 6370.49,2629 6378.95,2629 cw(c6378.95,2625.23) 6382.72,2625.23 ccw(c6386.49,2625.23) 6386.49,2621.47 6406,2621.47 6410,2625.47 v1(6410,2638.05)
MIPI_DPHY0_RX_D3N: J3.5 J32.20 | length 5817.7
  TOP w4.5: v2(1622.91,2218.88) 1633.5,2229.47 1685.96,2229.47 1700.52,2244.04 1700.52,2260.7 1703.65,2263.82 J3.5@1703.65,2286.88 ; v1(6360,2546.83) 6365.98,2552.82 cw(c6378.89,2539.91) 6378.89,2558.16 6493.34,2558.16 cw(c6493.34,2550.55) 6498.72,2555.93 6499.36,2555.3 ccw(c6504.74,2560.68) 6504.74,2553.07 J32.20@6533.11,2553.07
  ART03 w4: v2(1622.91,2218.88) 1632.75,2228.72 1644.06,2228.72 1655,2217.79 1655,2080.44 1687.44,2048 2086,2048 2242,2204 2538,2204 2675,2067 2946.31,2067 cw(c2946.31,2059) 2947.68,2066.88 3069.1,2045.8 ccw(c3072.35,2064.52) 3075.6,2045.8 3197.03,2066.88 ; 3197.03,2066.88 cw(c3198.39,2059) 3198.39,2067 3218.31,2067 cw(c3218.31,2059) 3219.68,2066.88 3329.88,2047.75 ccw(c3333.13,2066.47) 3336.38,2047.75 3446.58,2066.88 cw(c3447.95,2059) 3447.95,2067 3480.88,2067 3633.25,2093.45 3785.62,2067 3955.57,2067 4082.59,2089.05 4209.62,2067 4519,2067 4569,2117 4569,2199.31 cw(c4577,2199.31) 4569.12,2200.68 4584.46,2289.03 ccw(c4565.74,2292.28) 4584.46,2295.53 4569.12,2383.88 cw(c4577,2385.24) 4569,2385.24 4569,2416.44 4701.56,2549 5628,2549 5665,2586 5665,2623.44 5678.93,2637.37 6217.9,2637.37 6297.85,2557.41 6349.42,2557.41 v1(6360,2546.83)
MIPI_DPHY0_RX_D3P: J3.3 J32.19 | length 5818
  TOP w4.5: v2(1622.91,2249.56) 1633.5,2238.97 1682.02,2238.97 1691.02,2247.97 1691.02,2260.7 1687.9,2263.82 J3.3@1687.9,2286.88 ; v1(6360,2578.99) 6365.98,2573.01 ccw(c6378.89,2585.92) 6378.89,2567.66 6493.34,2567.66 ccw(c6493.34,2575.27) 6498.72,2569.89 6499.36,2570.53 cw(c6504.74,2565.14) 6504.74,2572.76 J32.19@6533.11,2572.76
  ART03 w4: v2(1622.91,2249.56) 1632.75,2239.72 1648.62,2239.72 1666,2222.34 1666,2085 1692,2059 1705.75,2059 ccw(c1705.75,2062.5) 1709.25,2062.5 cw(c1712.75,2062.5) 1712.75,2066 1721.75,2066 cw(c1721.75,2062.5) 1725.25,2062.5 ccw(c1728.75,2062.5) 1728.75,2059 1737.75,2059 ccw(c1737.75,2062.5) 1741.25,2062.5 cw(c1744.75,2062.5) 1744.75,2066 1753.75,2066 cw(c1753.75,2062.5) 1757.25,2062.5 ccw(c1760.75,2062.5) 1760.75,2059 2081.44,2059 2237.44,2215 2542.56,2215 2679.56,2078 2946.31,2078 cw(c2946.31,2059) 2949.56,2077.72 3070.98,2056.64 ccw(c3072.35,2064.52) 3073.72,2056.63 3195.14,2077.72 cw(c3198.39,2059) 3198.39,2078 3218.31,2078 cw(c3218.31,2059) 3221.56,2077.72 3331.76,2058.58 ccw(c3333.13,2066.47) 3334.5,2058.58 3444.7,2077.72 cw(c3447.95,2059) 3447.95,2078 3479.93,2078 3633.25,2104.62 3786.57,2078 3954.62,2078 4082.59,2100.22 4210.57,2078 4514.44,2078 4558,2121.56 4558,2199.31 cw(c4577,2199.31) 4558.28,2202.56 4573.62,2290.91 ccw(c4565.74,2292.28) 4573.62,2293.64 4558.28,2381.99 cw(c4577,2385.24) 4558,2385.24 4558,2421 4697,2560 5623.44,2560 5654,2590.56 5654,2628 5674.37,2648.37 6222.45,2648.37 6302.41,2568.41 6349.42,2568.41 v1(6360,2578.99)
MIPI_DPHY0_TX_CLKN: J3.41 J14.24 | length 2613.9
  TOP w4.5: J14.24@275.91,2542.26 307.43,2542.26 312.52,2547.36 342.5,2547.36 v1(353.83,2536.03) ; v1(1395,2050.17) 1405.33,2060.5 1422.52,2060.5 1433.36,2071.34 1433.36,2092.23 1438.63,2097.5 1446.09,2097.5 1451.36,2092.23 1451.36,2071.34 1462.19,2060.5 1936.93,2060.5 1983.99,2107.55 1983.99,2260.7 1987.11,2263.82 J3.41@1987.11,2286.88
  ART03 w4: v1(353.83,2536.03) 363.8,2546 439,2546 447,2538 447,2515.51 458.13,2504.38 499.31,2504.38 504,2499.69 504,2493.06 499.31,2488.38 458.13,2488.38 447,2477.25 447,2461.51 458.13,2450.38 499.31,2450.38 504,2445.69 504,2439.06 499.31,2434.38 458.13,2434.38 447,2423.25 447,2403.44 461.44,2389 588,2389 596,2381 596,2204 612,2188 841.44,2188 849,2180.44 849,2084 862,2071 1316.38,2071 1326.63,2060.75 1384.42,2060.75 v1(1395,2050.17)
MIPI_DPHY0_TX_CLKP: J3.39 J14.23 | length 2613.7
  TOP w4.5: J14.23@275.91,2561.95 307.43,2561.95 312.52,2556.86 342.5,2556.86 v1(353.83,2568.19) ; v1(1395,2082.33) 1407.33,2070 1418.59,2070 1423.86,2075.27 1423.86,2096.16 1434.69,2107 1450.02,2107 1460.86,2096.16 1460.86,2075.27 1466.13,2070 1933,2070 1974.49,2111.49 1974.49,2217.22 ccw(c1968.24,2217.22) 1968.24,2223.47 cw(c1968.24,2229.71) 1962,2229.71 1962,2235.22 cw(c1968.24,2235.22) 1968.24,2241.47 ccw(c1968.24,2247.71) 1974.49,2247.71 1974.49,2260.7 1971.36,2263.82 J3.39@1971.36,2286.88
  ART03 w4: v1(353.83,2568.19) 365.02,2557 443.56,2557 458,2542.56 458,2520.06 462.69,2515.38 503.87,2515.38 515,2504.25 515,2488.51 503.87,2477.38 462.69,2477.38 458,2472.69 458,2466.06 462.69,2461.38 503.87,2461.38 515,2450.25 515,2434.51 503.87,2423.38 462.69,2423.38 458,2418.69 458,2408 466,2400 592.56,2400 607,2385.56 607,2208.56 616.56,2199 846,2199 860,2185 860,2088.56 866.56,2082 1320.94,2082 1331.19,2071.75 1384.42,2071.75 v1(1395,2082.33)
MIPI_DPHY0_TX_D0N: J3.51 J14.27 | length 2614.4
  TOP w4.5: J14.27@275.91,2483.21 307.43,2483.21 312.52,2488.3 364.67,2488.3 v1(377,2475.97) ; v1(1560,1959.17) 1571.33,1970.5 1627.73,1970.5 1633,1965.23 1633,1946.84 1643.84,1936 1659.17,1936 1670,1946.84 1670,1965.23 1675.28,1970.5 1684.78,1970.5 1690.05,1965.23 1690.05,1951.84 1700.88,1941 1716.21,1941 1727.05,1951.84 1727.05,1965.23 1732.32,1970.5 1958.5,1970.5 2062.73,2074.73 2062.73,2260.7 2065.85,2263.82 J3.51@2065.85,2286.88
  ART03 w4: v1(377,2475.97) 388.58,2487.55 400,2487.55 408,2479.55 408,2370.44 422.44,2356 555.44,2356 567,2344.44 567,2169 582,2154 796.44,2154 809.27,2141.17 809.27,2041.17 822.5,2027.94 1316.5,2027.94 1324,2020.44 1324,1986.44 1337.44,1973 1546.17,1973 v1(1560,1959.17)
MIPI_DPHY0_TX_D0P: J3.49 J14.26 | length 2617.2
  TOP w4.5: J14.26@275.91,2502.89 307.43,2502.89 312.52,2497.8 366.67,2497.8 v1(377,2508.13) ; v1(1560,1991.33) 1571.33,1980 1631.67,1980 1642.5,1969.16 1642.5,1950.77 1647.78,1945.5 1655.23,1945.5 1660.5,1950.77 1660.5,1969.16 1671.34,1980 1688.71,1980 1699.55,1969.16 1699.55,1955.77 1704.82,1950.5 1712.28,1950.5 1717.55,1955.77 1717.55,1969.16 1728.38,1980 1954.56,1980 2053.23,2078.66 2053.23,2260.7 2050.1,2263.82 J3.49@2050.1,2286.88
  ART03 w4: v1(377,2508.13) 386.58,2498.55 404.56,2498.55 419,2484.11 419,2375 427,2367 560,2367 578,2349 578,2173.56 586.56,2165 801,2165 820.27,2145.73 820.27,2045.73 827.06,2038.94 1321.06,2038.94 1335,2025 1335,1991 1342,1984 1354.34,1984 ccw(c1354.34,1989) 1359.34,1989 cw(c1364.34,1989) 1364.34,1994 1370.34,1994 cw(c1370.34,1989) 1375.34,1989 ccw(c1380.34,1989) 1380.34,1984 1386.34,1984 ccw(c1386.34,1989) 1391.34,1989 cw(c1396.34,1989) 1396.34,1994 1402.34,1994 cw(c1402.34,1989) 1407.34,1989 ccw(c1412.34,1989) 1412.34,1984 1552.67,1984 v1(1560,1991.33)
MIPI_DPHY0_TX_D1N: J3.47 J14.21 | length 2612.6
  TOP w4.5: J14.21@275.91,2601.32 307.43,2601.32 312.52,2606.41 372.5,2606.41 v1(383.83,2595.08) ; v1(1485,2004.17) 1496.33,2015.5 1947.5,2015.5 2031.23,2099.23 2031.23,2260.7 2034.36,2263.82 J3.47@2034.36,2286.88
  ART03 w4: v1(383.83,2595.08) 394.41,2605.66 524.78,2605.66 533,2597.44 533,2588.44 528.31,2583.76 493.13,2583.76 482,2572.63 482,2556.89 493.13,2545.76 528.31,2545.76 533,2541.07 533,2435.44 547.44,2421 621.48,2421 636.52,2405.96 636.52,2251.48 651.11,2236.89 879.55,2236.89 887,2229.44 887,2133.44 899.44,2121 1397.44,2121 1415,2103.44 1415,2029.19 1429.44,2014.75 1474.42,2014.75 v1(1485,2004.17)
MIPI_DPHY0_TX_D1P: J3.45 J14.20 | length 2613.6
  TOP w4.5: J14.20@275.91,2621 307.43,2621 312.52,2615.91 372.5,2615.91 v1(383.83,2627.24) ; v1(1485,2036.33) 1496.33,2025 1943.56,2025 2021.73,2103.17 2021.73,2260.7 2018.61,2263.82 J3.45@2018.61,2286.88
  ART03 w4: v1(383.83,2627.24) 394.41,2616.66 459.06,2616.66 ccw(c459.06,2620.33) 462.73,2620.33 cw(c466.4,2620.33) 466.4,2624 475.06,2624 cw(c475.06,2620.33) 478.73,2620.33 ccw(c482.4,2620.33) 482.4,2616.66 491.06,2616.66 ccw(c491.06,2620.33) 494.73,2620.33 cw(c498.4,2620.33) 498.4,2624 507.06,2624 cw(c507.06,2620.33) 510.73,2620.33 ccw(c514.4,2620.33) 514.4,2616.66 529.34,2616.66 544,2602 544,2583.89 532.87,2572.76 497.69,2572.76 493,2568.07 493,2561.44 497.69,2556.76 532.87,2556.76 544,2545.63 544,2440 552,2432 626.04,2432 647.52,2410.52 647.52,2256.04 655.67,2247.89 884.11,2247.89 898,2234 898,2138 904,2132 1402,2132 1426,2108 1426,2033.75 1434,2025.75 1474.42,2025.75 v1(1485,2036.33)
MIPI_DPHY0_TX_D2N: J3.35 J14.18 | length 2613
  TOP w4.5: J14.18@275.91,2660.38 307.43,2660.38 312.52,2665.47 339.15,2665.47 v1(350.48,2654.14) ; v1(1485,2093.67) 1496.83,2105.5 1882.5,2105.5 1936.74,2159.74 1936.74,2260.7 1939.87,2263.82 J3.35@1939.87,2286.88
  ART03 w4: v1(350.48,2654.14) 361.06,2664.72 387.28,2664.72 404.97,2647.03 556,2647.03 564,2639.03 564,2466.44 578.44,2452 661.44,2452 676,2437.44 676,2291 691,2276 909.44,2276 921,2264.44 921,2170 937,2154 965.24,2154 976.37,2165.13 976.37,2189.31 981.06,2194 987.69,2194 992.37,2189.31 992.37,2164.63 1003,2154 1022.24,2154 1033.37,2165.13 1033.37,2189.31 1038.06,2194 1044.69,2194 1049.37,2189.31 1049.37,2165.13 1060.5,2154 1076.24,2154 1087.37,2165.13 1087.37,2190 1091.37,2194 1099.37,2194 1103.37,2190 1103.37,2165.13 1114.5,2154 1182.94,2154 1194.07,2165.13 1194.07,2188.31 1198.76,2193 1205.38,2193 1210.07,2188.31 1210.07,2165.13 1221.2,2154 1241.42,2154 1252.55,2165.13 1252.55,2189.31 1257.23,2194 1263.86,2194 1268.55,2189.31 1268.55,2165.13 1279.67,2154 1405.44,2154 1455.19,2104.25 1474.42,2104.25 v1(1485,2093.67)
MIPI_DPHY0_TX_D2P: J3.33 J14.17 | length 2615.1
  TOP w4.5: J14.17@275.91,2680.06 307.43,2680.06 312.52,2674.97 339.15,2674.97 v1(350.48,2686.3) ; v1(1485,2125.83) 1495.83,2115 1878.56,2115 1927.24,2163.68 1927.24,2260.7 1924.12,2263.82 J3.33@1924.12,2286.88
  ART03 w4: v1(350.48,2686.3) 361.06,2675.72 391.84,2675.72 409.52,2658.03 418.52,2658.03 ccw(c418.52,2662.02) 422.51,2662.02 cw(c426.49,2662.02) 426.49,2666 434.52,2666 cw(c434.52,2662.02) 438.51,2662.02 ccw(c442.49,2662.02) 442.49,2658.03 450.52,2658.03 ccw(c450.52,2662.02) 454.51,2662.02 cw(c458.49,2662.02) 458.49,2666 466.52,2666 cw(c466.52,2662.02) 470.51,2662.02 ccw(c474.49,2662.02) 474.49,2658.03 560.56,2658.03 575,2643.59 575,2471 583,2463 666,2463 687,2442 687,2295.56 695.56,2287 914,2287 932,2269 932,2174.56 941.56,2165 960.69,2165 965.37,2169.69 965.37,2193.87 976.5,2205 992.24,2205 1003.37,2193.87 1003.37,2169.18 1007.56,2165 1017.69,2165 1022.37,2169.69 1022.37,2193.87 1033.5,2205 1049.24,2205 1060.37,2193.87 1060.37,2169.69 1065.06,2165 1071.69,2165 1076.37,2169.69 1076.37,2194.56 1086.82,2205 1103.93,2205 1114.37,2194.56 1114.37,2169.69 1119.06,2165 1178.38,2165 1183.07,2169.69 1183.07,2192.87 1194.2,2204 1209.94,2204 1221.07,2192.87 1221.07,2169.69 1225.76,2165 1236.86,2165 1241.55,2169.69 1241.55,2193.87 1252.67,2205 1268.42,2205 1279.55,2193.87 1279.55,2169.69 1284.23,2165 1410,2165 1459.75,2115.25 1474.42,2115.25 v1(1485,2125.83)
